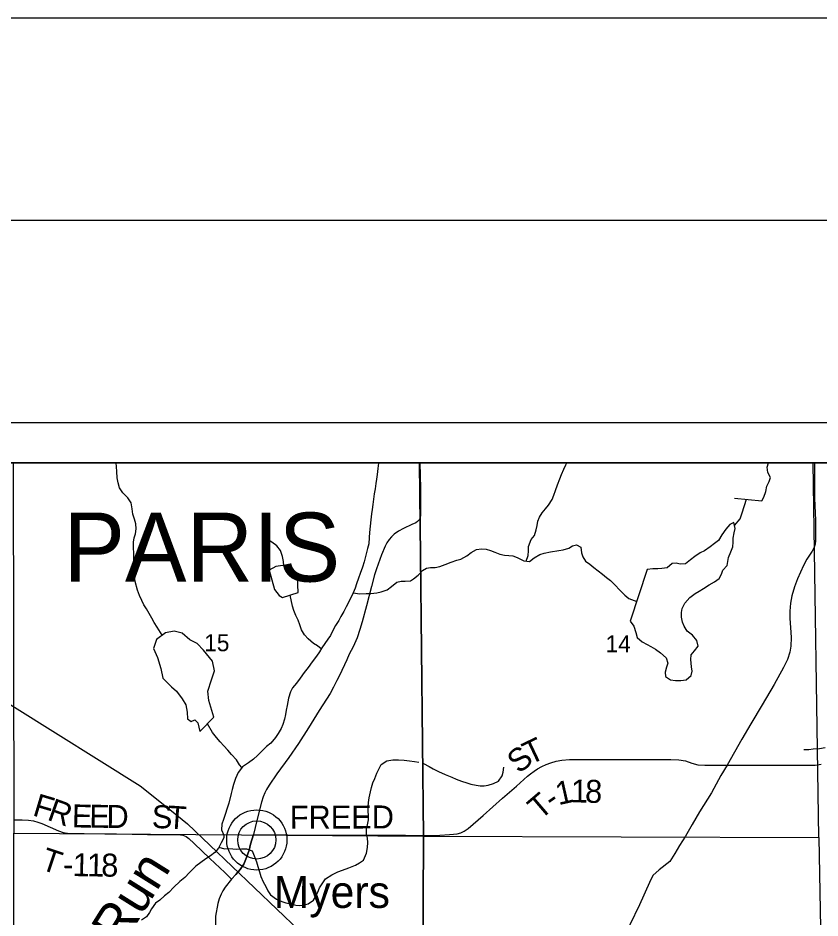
# Model space of a CAD drawing. Extents: x 0 to 34, y 0 to 22.
# Drawn here: x 3.267 to 5.25, y 19.775 to 22 of the extents above; entities that cross this region are included whole.
import ezdxf

# ---------------------------------------------------------------- set-up
doc = ezdxf.new("R2010")
doc.units = 0
for name, color, linetype in [('Default', 7, 'Continuous'), ('SH_Border', 7, 'Continuous'), ('SH_Cut_Line', 7, 'Continuous'), ('SH_Data', 7, 'Continuous')]:
    doc.layers.add(name, color=color, linetype=linetype)

msp = doc.modelspace()

# ---------------------------------------------------------------- linework, layer by layer
at = {"layer": 'Default'}
msp.add_line((3.8575, 19.9676), (3.8575, 19.9676), dxfattribs=at)
for points in [[(6.2766, 18.3021), (6.2705, 18.5012), (6.2432, 19.8937), (6.2315, 20.9), (2.1, 20.9)], [(3.6238, 20.474), (3.6116, 20.4939), (3.6035, 20.5052), (3.5977, 20.5158), (3.5911, 20.5275), (3.5852, 20.5388), (3.5783, 20.5489), (3.5736, 20.5595), (3.5677, 20.572), (3.5626, 20.5856), (3.557, 20.6068), (3.5553, 20.617), (3.554, 20.6269), (3.5535, 20.6363), (3.5537, 20.6485), (3.5536, 20.658), (3.5538, 20.6747), (3.5524, 20.6918), (3.5526, 20.7043), (3.5547, 20.7146), (3.5576, 20.7246), (3.5593, 20.7371), (3.5588, 20.7489), (3.5548, 20.7606), (3.5509, 20.7735), (3.5495, 20.7864), (3.5471, 20.8008), (3.5385, 20.8139), (3.5262, 20.8259), (3.5177, 20.8383), (3.5149, 20.8505), (3.5125, 20.8626), (3.5111, 20.8785), (3.5106, 20.8899), (3.5095, 20.9)], [(4.2608, 20.9), (4.2618, 20.8375), (4.2625, 20.7782), (4.2622, 20.7707), (4.2611, 20.7644), (4.2588, 20.7592), (4.2551, 20.7552), (4.2506, 20.7518), (4.2411, 20.7474), (4.2198, 20.7375), (4.2079, 20.7313), (4.1972, 20.7235), (4.1906, 20.7174), (4.185, 20.7108), (4.1791, 20.7023), (4.1746, 20.6939), (4.1659, 20.6723), (4.1534, 20.6381), (4.1487, 20.623), (4.1411, 20.5942), (4.1285, 20.5462), (4.1179, 20.5073), (4.1124, 20.488), (4.1054, 20.4677), (4.0957, 20.4454), (4.0861, 20.4267), (4.0797, 20.413), (4.0616, 20.3738), (4.0557, 20.3615), (4.0473, 20.3452), (4.0387, 20.33), (4.0117, 20.288), (3.9856, 20.2444), (3.9606, 20.2058), (3.9364, 20.1718), (3.9073, 20.1308), (3.8878, 20.1031), (3.8811, 20.0922), (3.8771, 20.0842), (3.8732, 20.0744), (3.8691, 20.0606), (3.8576, 20.0156), (3.849, 19.981)], [(4.1586, 20.9), (4.1585, 20.8992), (4.1568, 20.8862), (4.1551, 20.8714), (4.1534, 20.8596), (4.1516, 20.8489), (4.1499, 20.836), (4.1478, 20.8234), (4.1457, 20.8101), (4.144, 20.7968), (4.1427, 20.7846), (4.1409, 20.7739), (4.1396, 20.7595), (4.1379, 20.7435), (4.1359, 20.7279), (4.1349, 20.7157), (4.1348, 20.6994), (4.1311, 20.6879), (4.1254, 20.665), (4.1232, 20.6551), (4.1192, 20.6421), (4.113, 20.6265), (4.109, 20.615), (4.1043, 20.6005), (4.1006, 20.5902)], [(4.5232, 20.6573), (4.5281, 20.6712), (4.5294, 20.6823), (4.5292, 20.6933), (4.5361, 20.7105), (4.5442, 20.7206), (4.5485, 20.734), (4.5502, 20.7454), (4.5519, 20.7561), (4.5567, 20.766), (4.5633, 20.7761), (4.5711, 20.7861), (4.5789, 20.7957), (4.5878, 20.8096), (4.5922, 20.8199), (4.5961, 20.8318), (4.6012, 20.8456), (4.6066, 20.8601), (4.611, 20.8712), (4.6164, 20.8842), (4.6211, 20.8954), (4.6238, 20.9)], [(5.2362, 20.9), (5.2362, 20.8938), (5.2366, 20.813), (5.2388, 20.7577), (5.2388, 20.7201), (5.2388, 20.7081), (5.2376, 20.6986), (5.2345, 20.6894), (5.2303, 20.6814), (5.2175, 20.6617), (5.2089, 20.6464), (5.1943, 20.6133), (5.1868, 20.5937), (5.1805, 20.5708), (5.1772, 20.5527), (5.1749, 20.5335), (5.1749, 20.5149), (5.1767, 20.4931), (5.1787, 20.4685), (5.1777, 20.4469), (5.1754, 20.4317), (5.1693, 20.4139), (5.1596, 20.3941), (5.1365, 20.3519), (5.1066, 20.3019), (5.0791, 20.2549), (5.0566, 20.2164), (5.0206, 20.1521), (5.0048, 20.1273), (4.9815, 20.0841), (4.9518, 20.037), (4.9334, 20.0058), (4.9177, 19.9768), (4.9022, 19.9536), (4.8913, 19.9338), (4.8823, 19.9212), (4.8782, 19.9143), (4.8525, 19.8937), (4.8366, 19.8795), (4.8287, 19.8624), (4.8036, 19.8068), (4.732, 19.6587)], [(5.1064, 20.8057), (5.1108, 20.8152), (5.1155, 20.829), (5.1187, 20.8424), (5.1238, 20.8535), (5.1278, 20.8634), (5.121, 20.8762), (5.1193, 20.8891), (5.1223, 20.9)], [(5.0385, 20.7452), (5.0525, 20.7617), (5.0572, 20.7762), (5.068, 20.8099)], [(5.0386, 20.8131), (5.1064, 20.8057)], [(4.7808, 20.5082), (4.7898, 20.4962), (4.7943, 20.4804), (4.7975, 20.4683), (4.8099, 20.4575), (4.8222, 20.4505), (4.8318, 20.4461), (4.8434, 20.4395), (4.8557, 20.4303), (4.8693, 20.4176), (4.8737, 20.4044), (4.8705, 20.3948), (4.8669, 20.3826), (4.8679, 20.3716), (4.8802, 20.3635), (4.8928, 20.3622), (4.9058, 20.3617), (4.919, 20.3631), (4.9314, 20.3744), (4.9335, 20.385), (4.9321, 20.3957), (4.9302, 20.4139), (4.9315, 20.4249), (4.9397, 20.4349), (4.949, 20.4465), (4.9453, 20.4605), (4.9344, 20.474), (4.9217, 20.4836), (4.9142, 20.496), (4.9098, 20.5062), (4.9077, 20.5183), (4.9074, 20.5301), (4.9092, 20.54), (4.9154, 20.553), (4.9284, 20.567), (4.9412, 20.5771), (4.9509, 20.583), (4.9615, 20.5893), (4.9758, 20.5983), (4.9889, 20.6058), (5.0009, 20.6144), (5.0061, 20.6251), (5.0093, 20.6347), (5.0205, 20.6459), (5.0222, 20.6558), (5.0232, 20.6657), (5.029, 20.6799), (5.0344, 20.6925), (5.0354, 20.7036), (5.0352, 20.7138), (5.0379, 20.7272), (5.0404, 20.7379), (5.0367, 20.7526), (5.0269, 20.7475), (5.0168, 20.7363), (5.0072, 20.722), (4.9987, 20.7082), (4.9886, 20.7004), (4.9785, 20.6926), (4.9642, 20.6824), (4.9533, 20.6773), (4.9402, 20.6687), (4.93, 20.6605), (4.9173, 20.6507), (4.9044, 20.6497), (4.8944, 20.6518), (4.8846, 20.6508), (4.8718, 20.6403), (4.8586, 20.6386), (4.8487, 20.638), (4.8365, 20.6377), (4.8228, 20.6367)], [(3.9243, 20.645), (3.9238, 20.6557), (3.9213, 20.6686), (3.9158, 20.6837), (3.9069, 20.695), (3.895, 20.7035), (3.8832, 20.7117)], [(4.2566, 20.6222), (4.267, 20.6339), (4.2772, 20.6398), (4.2871, 20.6411), (4.2985, 20.6409), (4.3098, 20.6438), (4.3234, 20.6486), (4.3378, 20.6546), (4.3518, 20.6594), (4.3616, 20.6615), (4.3767, 20.6698), (4.3875, 20.6784), (4.4007, 20.6859), (4.4129, 20.6872), (4.4243, 20.6863), (4.4354, 20.6835), (4.4458, 20.6788), (4.4584, 20.6744), (4.4702, 20.672), (4.4809, 20.6707), (4.4908, 20.6701), (4.5012, 20.6662), (4.5177, 20.6581), (4.5314, 20.6561), (4.543, 20.6651), (4.5569, 20.6737), (4.5679, 20.677), (4.5834, 20.6803), (4.6039, 20.683), (4.6146, 20.6847), (4.6285, 20.6892), (4.6383, 20.6947), (4.6482, 20.6972), (4.6586, 20.6913), (4.6604, 20.6772), (4.6632, 20.6674), (4.6703, 20.6573), (4.6807, 20.6491), (4.6907, 20.6414), (4.712, 20.6251), (4.722, 20.6169), (4.7321, 20.6091), (4.7425, 20.5983), (4.7546, 20.5856), (4.767, 20.5726), (4.7771, 20.5644), (4.7969, 20.5574)], [(3.9597, 20.5791), (3.9584, 20.6174), (3.9503, 20.6318), (3.938, 20.6411), (3.9216, 20.6458), (3.9042, 20.644), (3.888, 20.6347), (3.9016, 20.587), (3.9128, 20.5723), (3.9212, 20.5671)], [(4.8228, 20.6367), (4.7808, 20.5082)], [(4.0959, 20.5788), (4.1122, 20.5759), (4.1277, 20.5769), (4.1391, 20.5767), (4.1543, 20.5784), (4.1652, 20.5809), (4.1796, 20.5864), (4.1904, 20.5942), (4.2036, 20.6054), (4.2145, 20.6074), (4.224, 20.6076), (4.2373, 20.6081), (4.245, 20.613), (4.2566, 20.6222)], [(2.781, 20.587), (3.2581, 20.2961), (3.5691, 20.1012), (3.6469, 20.0395), (3.6858, 20.0076), (4.1277, 19.5854), (4.2882, 19.4298), (4.7959, 18.9483), (4.8867, 18.8627), (4.9397, 18.8161), (4.9914, 18.7791), (5.0638, 18.7415), (5.1188, 18.7201), (5.1744, 18.7071), (5.2205, 18.7028), (5.2754, 18.7016), (5.3374, 18.6952), (5.4602, 18.6836), (5.597, 18.6827), (5.698, 18.6656), (5.9841, 18.6456), (6.1617, 18.6371), (6.2768, 18.6314)], [(4.1006, 20.5902), (4.0959, 20.5787), (4.0888, 20.565), (4.0781, 20.5443), (4.073, 20.5328), (4.0656, 20.5198), (4.06, 20.5098), (4.0522, 20.4976), (4.0448, 20.4838), (4.0397, 20.4735), (4.033, 20.4639), (4.0259, 20.4531), (4.0185, 20.4428), (4.0122, 20.4328), (4.0051, 20.4221), (3.9943, 20.4078), (3.9843, 20.3944), (3.9746, 20.3814), (3.9646, 20.3675), (3.9553, 20.3549), (3.9455, 20.3437), (3.9408, 20.3341), (3.936, 20.3185), (3.9325, 20.3002), (3.9304, 20.2888), (3.9286, 20.2781), (3.9258, 20.2663), (3.9222, 20.2529), (3.9181, 20.2434), (3.9107, 20.2308), (3.9036, 20.2212), (3.8921, 20.2073), (3.8816, 20.1988), (3.87, 20.1869), (3.8595, 20.1765), (3.849, 20.1672), (3.837, 20.1579), (3.8224, 20.1486), (3.8116, 20.134), (3.8046, 20.1194), (3.7998, 20.1049), (3.797, 20.0927), (3.7945, 20.0824), (3.788, 20.0588), (3.784, 20.0462), (3.7789, 20.0305), (3.7749, 20.018), (3.7709, 20.0069), (3.7703, 19.9928), (3.7758, 19.9796), (3.7763, 19.9731), (3.7696, 19.9605), (3.763, 19.9475), (3.7536, 19.9367), (3.7428, 19.9282), (3.7315, 19.9208), (3.7195, 19.9119), (3.7071, 19.9026), (3.6914, 19.8868), (3.6794, 19.8745), (3.667, 19.8648), (3.6528, 19.8509), (3.6397, 19.8375), (3.6292, 19.829), (3.618, 19.8189), (3.6071, 19.8115), (3.5975, 19.7973), (3.5923, 19.7878), (3.5852, 19.7778), (3.5721, 19.7689)], [(3.9212, 20.5671), (3.9597, 20.5791)], [(4.017, 20.4404), (4.0074, 20.4475), (3.9979, 20.4535), (3.9841, 20.4647), (3.9756, 20.4744), (3.9678, 20.4873), (3.9642, 20.4994), (3.9599, 20.5111), (3.9544, 20.5224), (3.9493, 20.5352), (3.9461, 20.5455), (3.9403, 20.573)], [(3.7516, 20.2714), (3.7389, 20.3123), (3.7363, 20.3358), (3.7454, 20.3633), (3.7527, 20.3858), (3.7482, 20.4097), (3.7258, 20.4367), (3.7097, 20.4536), (3.6921, 20.4624), (3.6729, 20.4792), (3.6531, 20.4839), (3.6316, 20.4798), (3.6098, 20.4635), (3.6021, 20.4406), (3.6123, 20.4187), (3.6199, 20.3915), (3.6248, 20.368), (3.6467, 20.3459), (3.6594, 20.3351), (3.6733, 20.3166), (3.6818, 20.3019), (3.6855, 20.2834), (3.6865, 20.2667), (3.6953, 20.2607), (3.7043, 20.2643), (3.712, 20.2575), (3.7165, 20.236)], [(3.7165, 20.236), (3.7516, 20.2714)], [(3.8208, 20.1465), (3.8147, 20.153), (3.8077, 20.1658), (3.795, 20.1789), (3.7858, 20.1895), (3.7758, 20.2003), (3.7673, 20.2101), (3.758, 20.221), (3.7484, 20.2334), (3.7354, 20.255)], [(5.2624, 20.195), (5.2484, 20.1932), (5.2332, 20.1918), (5.2218, 20.1908), (5.2096, 20.1902)], [(3.764, 19.9495), (3.7774, 19.9458), (3.7869, 19.9463), (3.7979, 19.9457), (3.8085, 19.9451), (3.8195, 19.9456), (3.8324, 19.9458), (3.8461, 19.9403), (3.8528, 19.9245), (3.8571, 19.9131), (3.8599, 19.9018), (3.8643, 19.8885), (3.8675, 19.8772), (3.8734, 19.8636), (3.88, 19.8527), (3.885, 19.8421), (3.8916, 19.8316), (3.9066, 19.8208), (3.9195, 19.8156), (3.9294, 19.8123), (3.9405, 19.8095), (3.9538, 19.8066), (3.9637, 19.8056), (3.9746, 19.8073), (3.9845, 19.8093), (3.998, 19.8186), (4.0035, 19.8286), (4.008, 19.8385), (4.0127, 19.8489), (4.0205, 19.8619), (4.0276, 19.8715), (4.0426, 19.8816), (4.0581, 19.8886), (4.0694, 19.8926), (4.0852, 19.8989), (4.1011, 19.9056), (4.1112, 19.9107), (4.1214, 19.9177), (4.1283, 19.9345), (4.1308, 19.9486), (4.1321, 19.9611), (4.1312, 19.9718), (4.1288, 19.9831), (4.129, 19.9941), (4.1315, 20.0052), (4.1333, 20.0174), (4.1328, 20.0497), (4.1338, 20.0603), (4.1355, 20.0717), (4.1387, 20.0866), (4.1409, 20.0973), (4.1445, 20.1087), (4.1489, 20.1194), (4.1544, 20.1324), (4.1647, 20.1538), (4.179, 20.1628), (4.1941, 20.166), (4.2074, 20.1655), (4.2218, 20.1649), (4.2351, 20.1632), (4.2477, 20.1619), (4.2579, 20.1597)], [(3.849, 19.981), (3.9341, 19.9804), (4.0402, 19.9796), (4.1366, 19.9794), (4.2252, 19.979), (4.2656, 19.9786), (4.2856, 19.9788), (4.3097, 19.9798), (4.3337, 19.9813), (4.344, 19.9819), (4.3528, 19.9831), (4.3619, 19.9855), (4.37, 19.9893), (4.3801, 19.9957), (4.4168, 20.0279), (4.4653, 20.071), (4.4992, 20.1009), (4.5266, 20.1253), (4.5338, 20.1311), (4.543, 20.1379), (4.5517, 20.1434), (4.5619, 20.1488), (4.5728, 20.1538), (4.584, 20.1581), (4.5973, 20.1621), (4.6118, 20.1647), (4.6302, 20.1664), (4.659, 20.1668), (4.7525, 20.1662), (4.819, 20.1667), (4.8547, 20.1665), (4.8811, 20.1664), (4.9005, 20.1656), (4.917, 20.1632), (4.9333, 20.1578), (4.948, 20.1535), (4.9653, 20.1521), (4.9854, 20.1521), (5.0206, 20.1521), (5.0641, 20.1523), (5.1887, 20.1524), (5.2378, 20.1528), (5.2524, 20.1548)], [(4.2694, 20.1566), (4.2833, 20.1493), (4.2936, 20.1434), (4.3063, 20.1368), (4.3232, 20.1292), (4.3397, 20.123), (4.3501, 20.1179), (4.3635, 20.1129), (4.3765, 20.1086), (4.3864, 20.1053), (4.4002, 20.1029), (4.4101, 20.1016), (4.4196, 20.1018), (4.4291, 20.1031), (4.4423, 20.1068), (4.4548, 20.1128), (4.4637, 20.1258), (4.4669, 20.1354), (4.4682, 20.1472)], [(3.2569, 20.0177), (3.2775, 20.0173), (3.2931, 20.0164), (3.3052, 20.015), (3.3163, 20.0119), (3.3262, 20.0079), (3.3676, 19.9898), (3.3789, 19.9859), (3.3898, 19.984), (3.4012, 19.9833), (3.4305, 19.9832), (3.5109, 19.9825), (3.5872, 19.9809), (3.6508, 19.9809), (3.6635, 19.9808), (3.6743, 19.9791), (3.6825, 19.976), (3.6893, 19.9715), (3.7028, 19.9589), (3.7418, 19.9219), (3.7782, 19.8872), (3.7949, 19.8708)], [(3.849, 19.981), (3.8422, 19.9568), (3.8385, 19.9425), (3.8321, 19.9242), (3.8252, 19.9081), (3.8165, 19.8944), (3.8056, 19.8822), (3.7949, 19.8708)], [(3.7949, 19.8708), (3.8056, 19.8822), (3.8165, 19.8944), (3.8252, 19.9081), (3.8321, 19.9242), (3.8385, 19.9425), (3.8422, 19.9568), (3.849, 19.981)], [(3.7949, 19.8708), (3.7793, 19.8505), (3.7736, 19.8419), (3.7693, 19.8339), (3.7648, 19.8223), (3.7614, 19.8101), (3.7555, 19.779), (3.7561, 19.722), (3.7559, 19.6337), (3.7546, 19.5245), (3.759, 19.3634)]]:
    msp.add_lwpolyline(points, dxfattribs=at)
for points in [[(4.26, 20.9), (3.255, 20.9), (3.2572, 19.9844), (4.2696, 19.9768)], [(5.2328, 20.9), (4.26, 20.9), (4.2696, 19.9768), (5.2472, 19.9737)], [(4.2696, 19.9768), (4.2649, 18.9814), (3.2565, 18.9852), (3.2572, 19.9844)], [(4.2696, 19.9768), (5.2472, 19.9737), (5.2648, 18.9869), (4.2649, 18.9814)]]:
    msp.add_lwpolyline(points, close=True, dxfattribs=at)
for radius in [0.0744, 0.0472]:
    msp.add_circle((3.8575, 19.9676), radius, dxfattribs=at)
at = {"layer": 'SH_Border'}
msp.add_lwpolyline([(1.5, 21.5), (33.5, 21.5), (33.5, 0.5), (1.5, 0.5)], close=True, dxfattribs=at)
at = {"layer": 'SH_Cut_Line'}
msp.add_lwpolyline([(0, 0), (34, 0), (34, 22), (0, 22)], close=True, dxfattribs=at)
msp.add_lwpolyline([(6.2766, 18.3021), (6.2705, 18.5012), (6.2432, 19.8937), (6.2315, 20.9), (2.1, 20.9)], dxfattribs=at)
at = {"layer": 'SH_Data'}
for p, q in [((2, 21), (9, 21)), ((2.1, 20.9), (8.9, 20.9))]:
    msp.add_line(p, q, dxfattribs=at)

# ---------------------------------------------------------------- texts
at = {"layer": 'Default'}
for s, height, rotation, p in [('PARIS', 0.17045, 0, (3.3796, 20.6065)), ('15', 0.04186, 0, (3.7275, 20.4342)), ('14', 0.04186, 0, (4.7196, 20.4315)), ('T', 0.0568, 25.4265, (4.5323, 20.1521)), ('S', 0.0568, 39.7788, (4.506, 20.1296)), ('1', 0.0568, 12.6982, (4.603, 20.0532)), ('1', 0.0568, 359.2611, (4.6337, 20.0605)), ('8', 0.0568, 358.2826, (4.6684, 20.06)), ('F', 0.0568, 343.46, (3.3009, 20.0288)), ('T', 0.0568, 40.4586, (4.5581, 20.0153)), ('-', 0.0568, 35.4397, (4.5894, 20.0421)), ('R', 0.0568, 340.4134, (3.3369, 20.0181)), ('E', 0.0568, 358.6542, (3.3999, 19.9989)), ('E', 0.0568, 359.4123, (3.4432, 19.9979)), ('D', 0.0568, 359.4219, (3.4857, 19.9975)), ('S', 0.0568, 359.1115, (3.5978, 19.9969)), ('T', 0.0568, 356.0842, (3.6353, 19.9963)), ('FREED', 0.05682, 0.2177, (3.9391, 19.9952)), ('T', 0.0568, 341.519, (3.32, 19.896)), ('1', 0.0568, 358.5173, (3.4017, 19.8784)), ('1', 0.0568, 359.3495, (3.4376, 19.8775)), ('Run', 0.09471, 57.9525, (3.5238, 19.7017)), ('8', 0.0568, 359.5517, (3.4728, 19.8771)), ('-', 0.0568, 357.801, (3.3776, 19.8793)), ('Myers', 0.07898, 0, (3.8992, 19.7995))]:
    msp.add_text(s, height=height, rotation=rotation, dxfattribs=at).set_placement(p)

doc.saveas('drawing.dxf')
